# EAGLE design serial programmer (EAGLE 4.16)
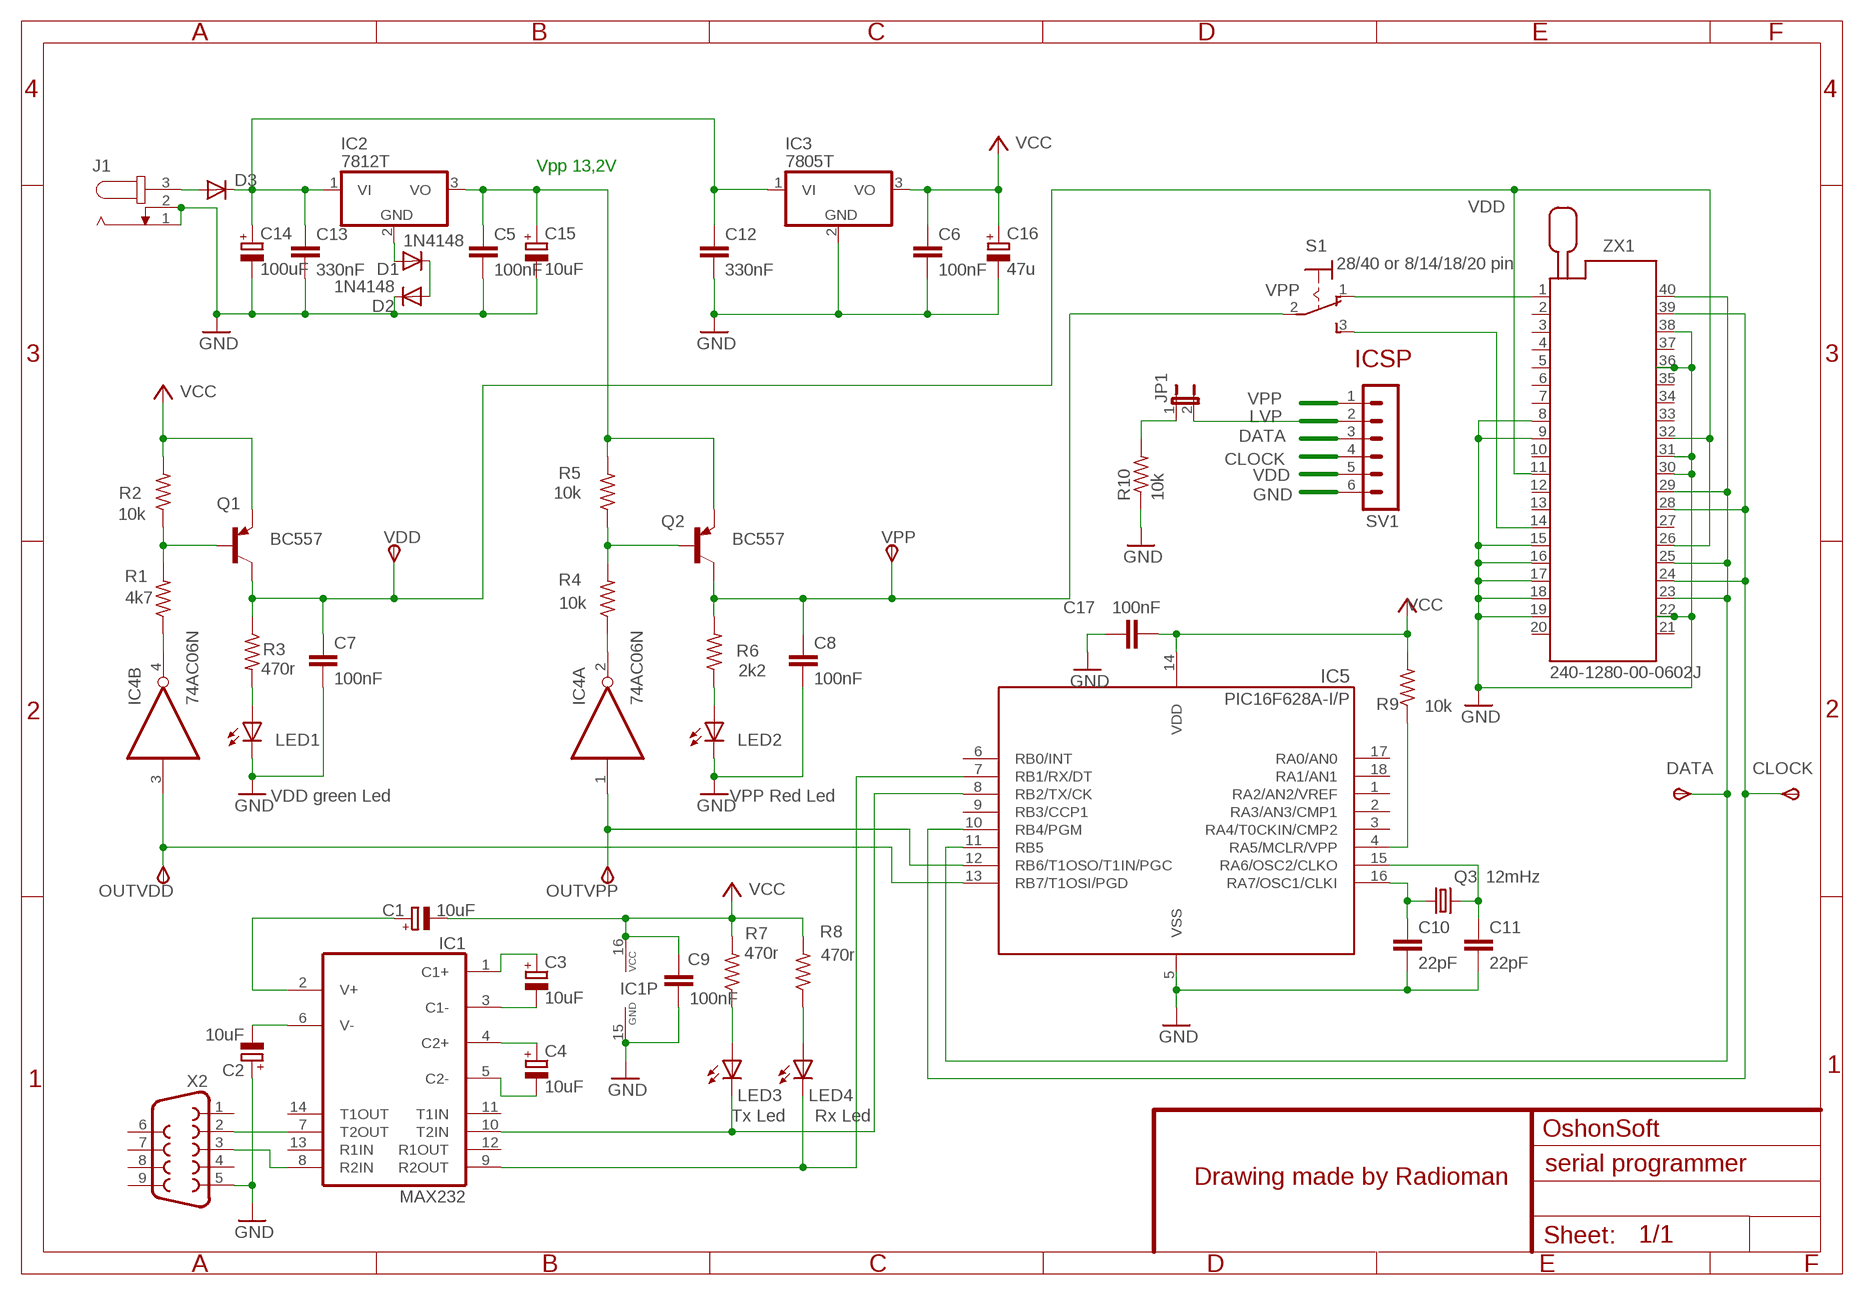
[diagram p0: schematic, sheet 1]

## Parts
C1  10uF  OVE_C_POL2MM_PAD10U25V  [E5-10,5]
C2  10uF  OVE_C_POL2MM_PAD10U25V  [E5-10,5]
C3  10uF  OVE_C_POL2MM_PAD10U25V  [E5-10,5]
C4  10uF  OVE_C_POL2MM_PAD10U25V  [E5-10,5]
C5  100nF  OVES_CGRID25X_050PAD15  [C025-025X050]
C6  100nF  OVES_CGRID25X_050PAD15  [C025-025X050]
C7  100nF  OVES_CGRID25X_050PAD15  [C025-025X050]
C8  100nF  OVES_CGRID25X_050PAD15  [C025-025X050]
C9  100nF  OVES_CGRID25X_050PAD15  [C025-025X050]
C10  22pF  OVES_CGRID25X_050PAD15  [C025-025X050]
C11  22pF  OVES_CGRID25X_050PAD15  [C025-025X050]
C12  330nF  OVES_CGRID75_2X_PAD20  [C075-052X106]
C13  330nF  OVES_CGRID75_2X_PAD20  [C075-052X106]
C14  100uF  OVE_C_POL2MM_PAD100U35V  [E3,5-8]
C15  10uF  OVE_C_POL2MM_PAD10U25V  [E5-10,5]
C16  47u  OVE_C_POL2MM_PAD47U35V  [E2,5-6E]
C17  100nF  OVES_CGRID25X_050PAD15  [C025-025X050]
CLOCK  OutVpp  TPSPAD1-13  [P1-13]
D1  1N4148  [DO35-10]
D2  1N4148  [DO35-10]
D3  1N4004  [DO41-10]
DATA  Data  TPSPAD1-13  [P1-13]
IC1  MAX232  [DIL16]
IC2  7812T  [TO220H]
IC3  7805T  [TO220H]
IC4  74AC06N  [DIL14]
IC5  PIC16F628A-I/P  [DIP18]
J1  JACK-PLUG1  [SPC4078]
JP1  JP1E  [JP1]
LED1  VDD green Led  LED3MM  [LED3MM]
LED2  VPP Red Led  LED3MM  [LED3MM]
LED3  Tx Led  LED3MM  [LED3MM]
LED4  Rx Led  LED3MM  [LED3MM]
OUTVDD  OutVdd  TPSPAD1-13  [P1-13]
OUTVPP  OutVpp  TPSPAD1-13  [P1-13]
Q1  BC557  [TO92-EBC]
Q2  BC557  [TO92-EBC]
Q3  12mHz  CRYSTALHC49S  [HC49/S]
R1  4k7  OVES_R10MM  [0207/10]
R2  10k  OVES_R10MM  [0207/10]
R3  470r  OVES_R10MM  [0207/10]
R4  10k  OVES_R10MM  [0207/10]
R5  10k  OVES_R10MM  [0207/10]
R6  2k2  OVES_R10MM  [0207/10]
R7  470r  OVES_R10MM  [0207/10]
R8  470r  OVES_R10MM  [0207/10]
R9  10k  OVES_R10MM  [0207/10]
R10  10k  OVES_R10MM  [0207/10]
S1  28/40 or 8/14/18/20 pin  320-916  [320-916]
SV1  MA06-1  [MA06-1]
VDD  Vdd  TPSPAD1-13  [P1-13]
VPP  Vpp  TPSPAD1-13  [P1-13]
X2  F09HP  [F09HP]
ZX1  240-1280-00-0602J  [240-1280-00-0602J]

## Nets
CLOCK: CLOCK.1(PP) IC5.10(RB4/PGM) SV1.4 ZX1.24 ZX1.28 ZX1.39
DATA: DATA.1(PP) IC5.11(RB5) SV1.3 ZX1.23 ZX1.25 ZX1.29 ZX1.40
GND: C2.+ C5.2 C6.2 C7.2 C8.2 C9.2 C10.2 C11.2 C12.2 C13.2 C14.- C15.- C16.- C17.1 D2.C IC1.15(GND) IC3.2(GND) IC5.5(VSS) J1.1 J1.2 LED1.K(C) LED2.K(C) R10.1 SV1.6 X2.5 ZX1.8 ZX1.9 ZX1.15 ZX1.16 ZX1.17 ZX1.18 ZX1.19 ZX1.22 ZX1.30 ZX1.31 ZX1.36 ZX1.38
LVP: JP1.2 SV1.2
N$1: D1.A IC2.2(GND)
N$2: C12.1 C13.1 C14.+ D3.C IC2.1(VI) IC3.1(VI)
N$3: D1.C D2.A
N$4: D3.A J1.3
N$5: LED3.A R7.1
N$6: Q1.B R1.2 R2.1
N$7: IC5.4(RA5/MCLR/VPP) R9.1
N$8: LED1.A R3.2
N$9: IC4.4(B:O) R1.1
N$10: Q2.B R4.2 R5.1
N$11: IC4.2(A:O) R4.1
N$12: C10.1 IC5.16(RA7/OSC1/CLKI) Q3.1
N$13: LED2.A R6.1
N$14: IC1.7(T2OUT) X2.2
N$15: IC1.8(R2IN) X2.3
N$16: LED4.A R8.1
N$17: IC1.10(T2IN) IC5.8(RB2/TX/CK) LED3.K(C)
N$18: IC1.9(R2OUT) IC5.7(RB1/RX/DT) LED4.K(C)
N$19: C1.+ IC1.2(V+)
N$20: C2.- IC1.6(V-)
N$21: C11.1 IC5.15(RA6/OSC2/CLKO) Q3.2
N$22: C4.- IC1.5(C2-)
N$23: C4.+ IC1.4(C2+)
N$24: C3.- IC1.3(C1-)
N$25: C3.+ IC1.1(C1+)
N$26: S1.1(O) ZX1.1
N$27: S1.3(S) ZX1.14
N$42: JP1.1 R10.2
OUTVDD: IC4.3(B:I) IC5.13(RB7/T1OSI/PGD) OUTVDD.1(PP)
OUTVPP: IC4.1(A:I) IC5.12(RB6/T1OSO/T1IN/PGC) OUTVPP.1(PP)
VCC: C1.- C6.1 C9.1 C16.+ C17.2 IC1.16(VCC) IC3.3(VO) IC5.14(VDD) Q1.E R2.2 R7.2 R8.2 R9.2
VDD: C7.1 Q1.C R3.1 SV1.5 VDD.1(PP) ZX1.11 ZX1.26 ZX1.32
VPP: C8.1 Q2.C R6.2 S1.2(P) SV1.1 VPP.1(PP)
VPP13.2V: C5.1 C15.+ IC2.3(VO) Q2.E R5.2
Unconnected: IC1.11(T1IN) IC1.12(R1OUT) IC1.13(R1IN) IC1.14(T1OUT) IC4.5(C:I) IC4.6(C:O) IC4.8(D:O) IC4.9(D:I) IC4.10(E:O) IC4.11(E:I) IC4.12(F:O) IC4.13(F:I) IC5.1(RA2/AN2/VREF) IC5.2(RA3/AN3/CMP1) IC5.3(RA4/T0CKIN/CMP2) IC5.6(RB0/INT) IC5.9(RB3/CCP1) IC5.17(RA0/AN0) IC5.18(RA1/AN1) X2.1 X2.4 X2.6 X2.7 X2.8 X2.9 ZX1.2 ZX1.3 ZX1.4 ZX1.5 ZX1.6 ZX1.7 ZX1.10 ZX1.12 ZX1.13 ZX1.20 ZX1.21 ZX1.27 ZX1.33 ZX1.34 ZX1.35 ZX1.37

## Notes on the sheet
- Vpp 13,2V
- ICSP
- OshonSoft
- Drawing made by Radioman

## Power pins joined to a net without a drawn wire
GND: IC4.7(P:GND)
VCC: IC4.14(P:VCC)

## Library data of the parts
C1-C4 C14-C16 = Oves-barebone:OVE_C_POL: De vanligaste med stora paddar.
C5-C13 C17 = Oves-barebone:OVES_C: De vanligaste med stora paddar.
CLOCK DATA OUTVDD OUTVPP VDD VPP = testpad:TPS: TEST PIN
D1 D2 = Oves-barebone:1N4148: DIODE
D3 = Oves-barebone:1N4004: DIODE
IC1 = maxim:MAX232: RS232 TRANSEIVER
IC2 IC3 = linear:78*: Positive VOLTAGE REGULATOR Source: http://cache.national.com/ds/LM/LM78L05.pdf http://www.fairchildsemi.com/ds/LM/LM7805.pdf
IC4 = 74xx-eu:74*06: Hex INVERTER, open collector high-voltage output
IC5 = pic:PIC16F628A-*/?: 18/20 pins, 2K prog, 224 RAM, 128 EEPROM, UART, 2 comp, 1 CCP
J1 = Oves-barebone:JACK-PLUG: DC POWER JACK Power Jack, DC, Right Angle, Through Hole, Rated 5A at 16VDC, PC Terminals Distributor: Farnell (www.Farnell.de) Drawing: 84N1161.pdf / 84N1162.pdf Manufacturer: SPC Technology (www.spctechnology.com) Type: SPC4077 / SPC 4078
JP1 = jumper:JP1E: JUMPER
LED1-LED4 = Oves-barebone:LED: LED
Q1 Q2 = transistor-pnp:BC557*: PNP Transistror
Q3 = crystal:CRYSTAL: CRYSTAL
R1-R10 = Oves-barebone:OVES_R: De vanligaste med stora paddar.
S1 = switch:320-916: TOGGLE SWITCH distributor RS Components
SV1 = con-lstb:MA06-1: PIN HEADER
X2 = con-subd:F09: SUB-D
ZX1 = con-3m:240-?-00-0602J: Zero Insertion Force Socked Source: http://www.3M.com/ehpd

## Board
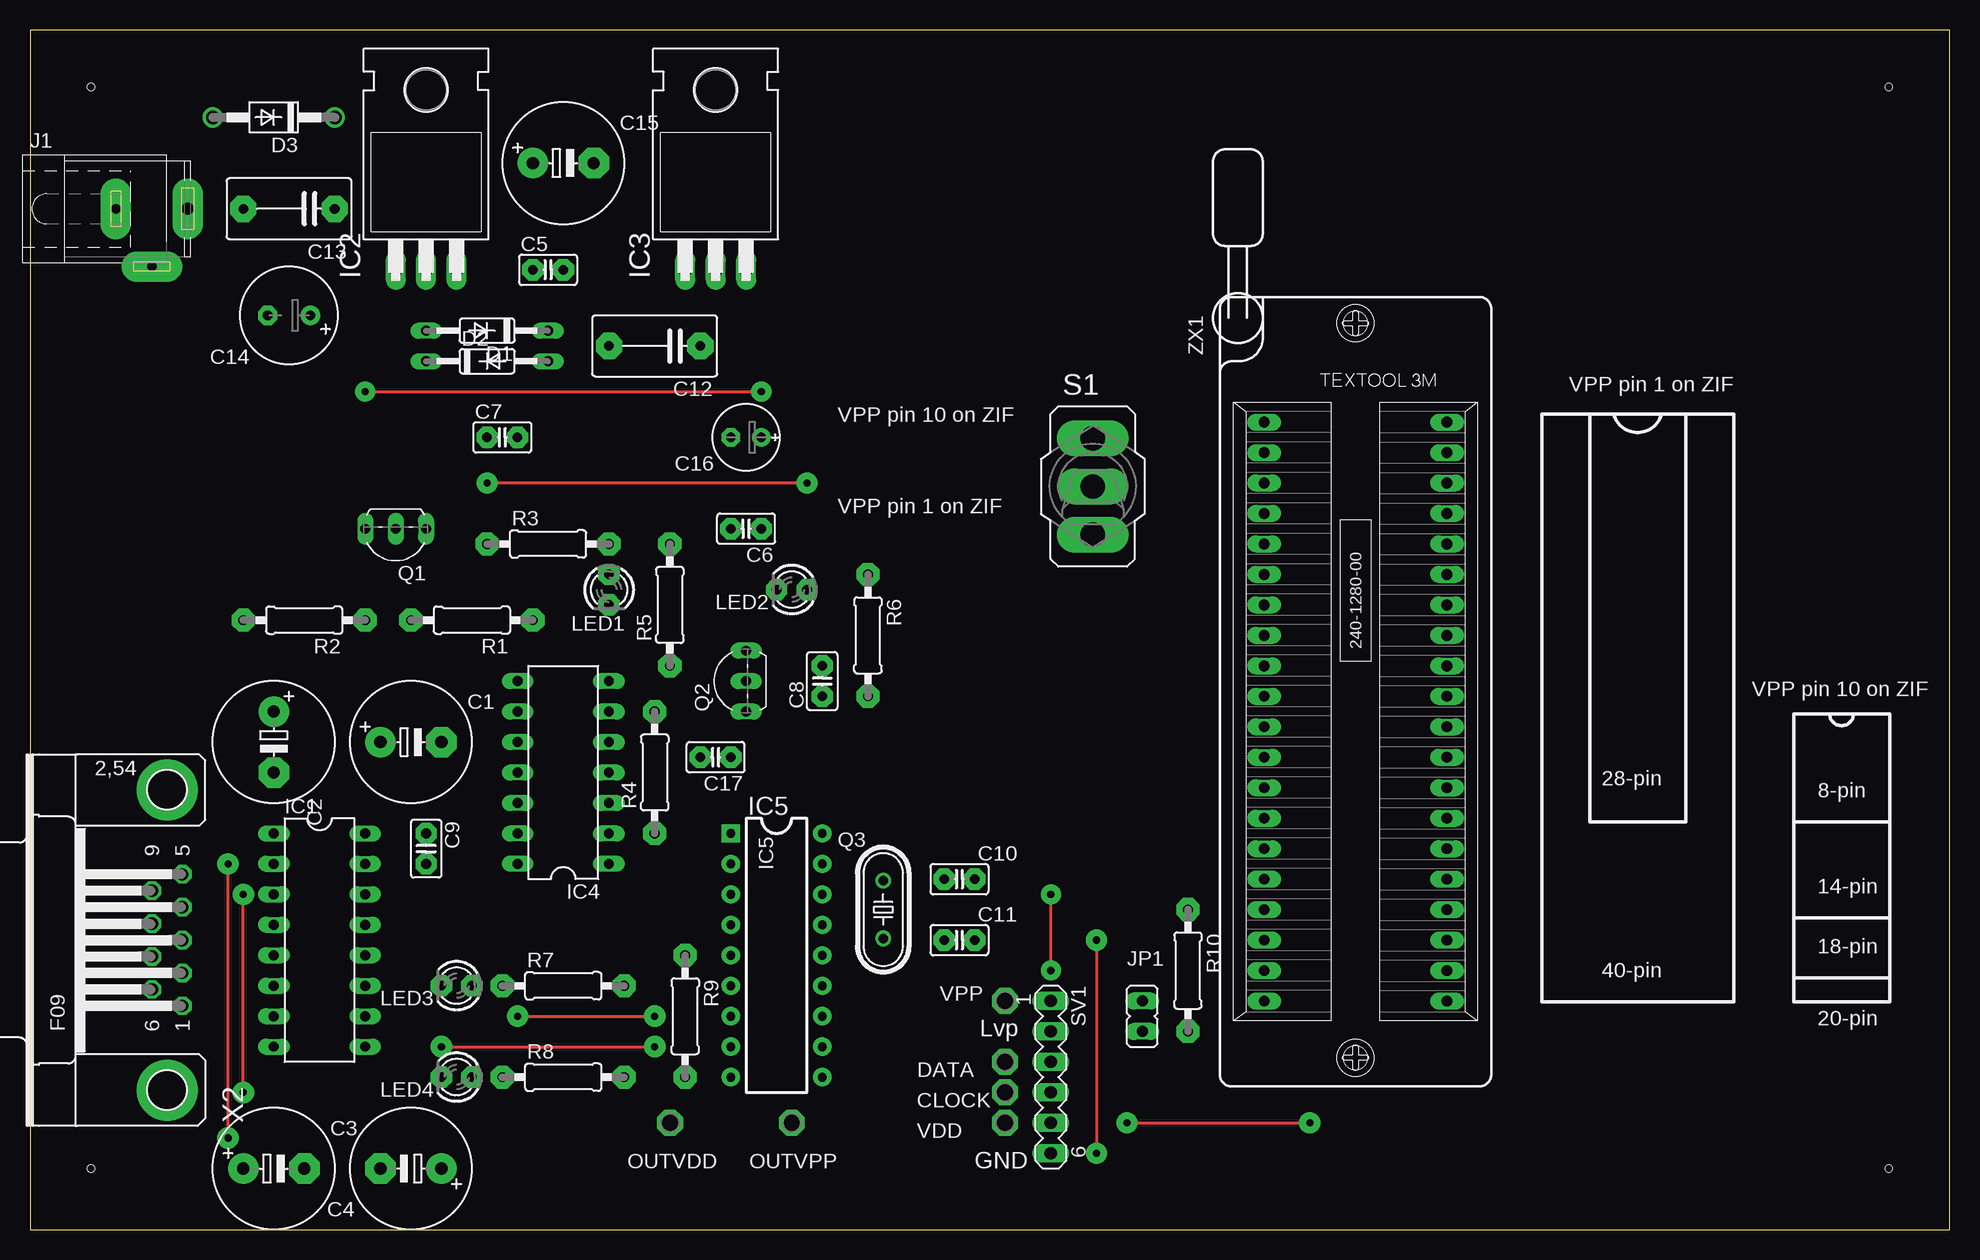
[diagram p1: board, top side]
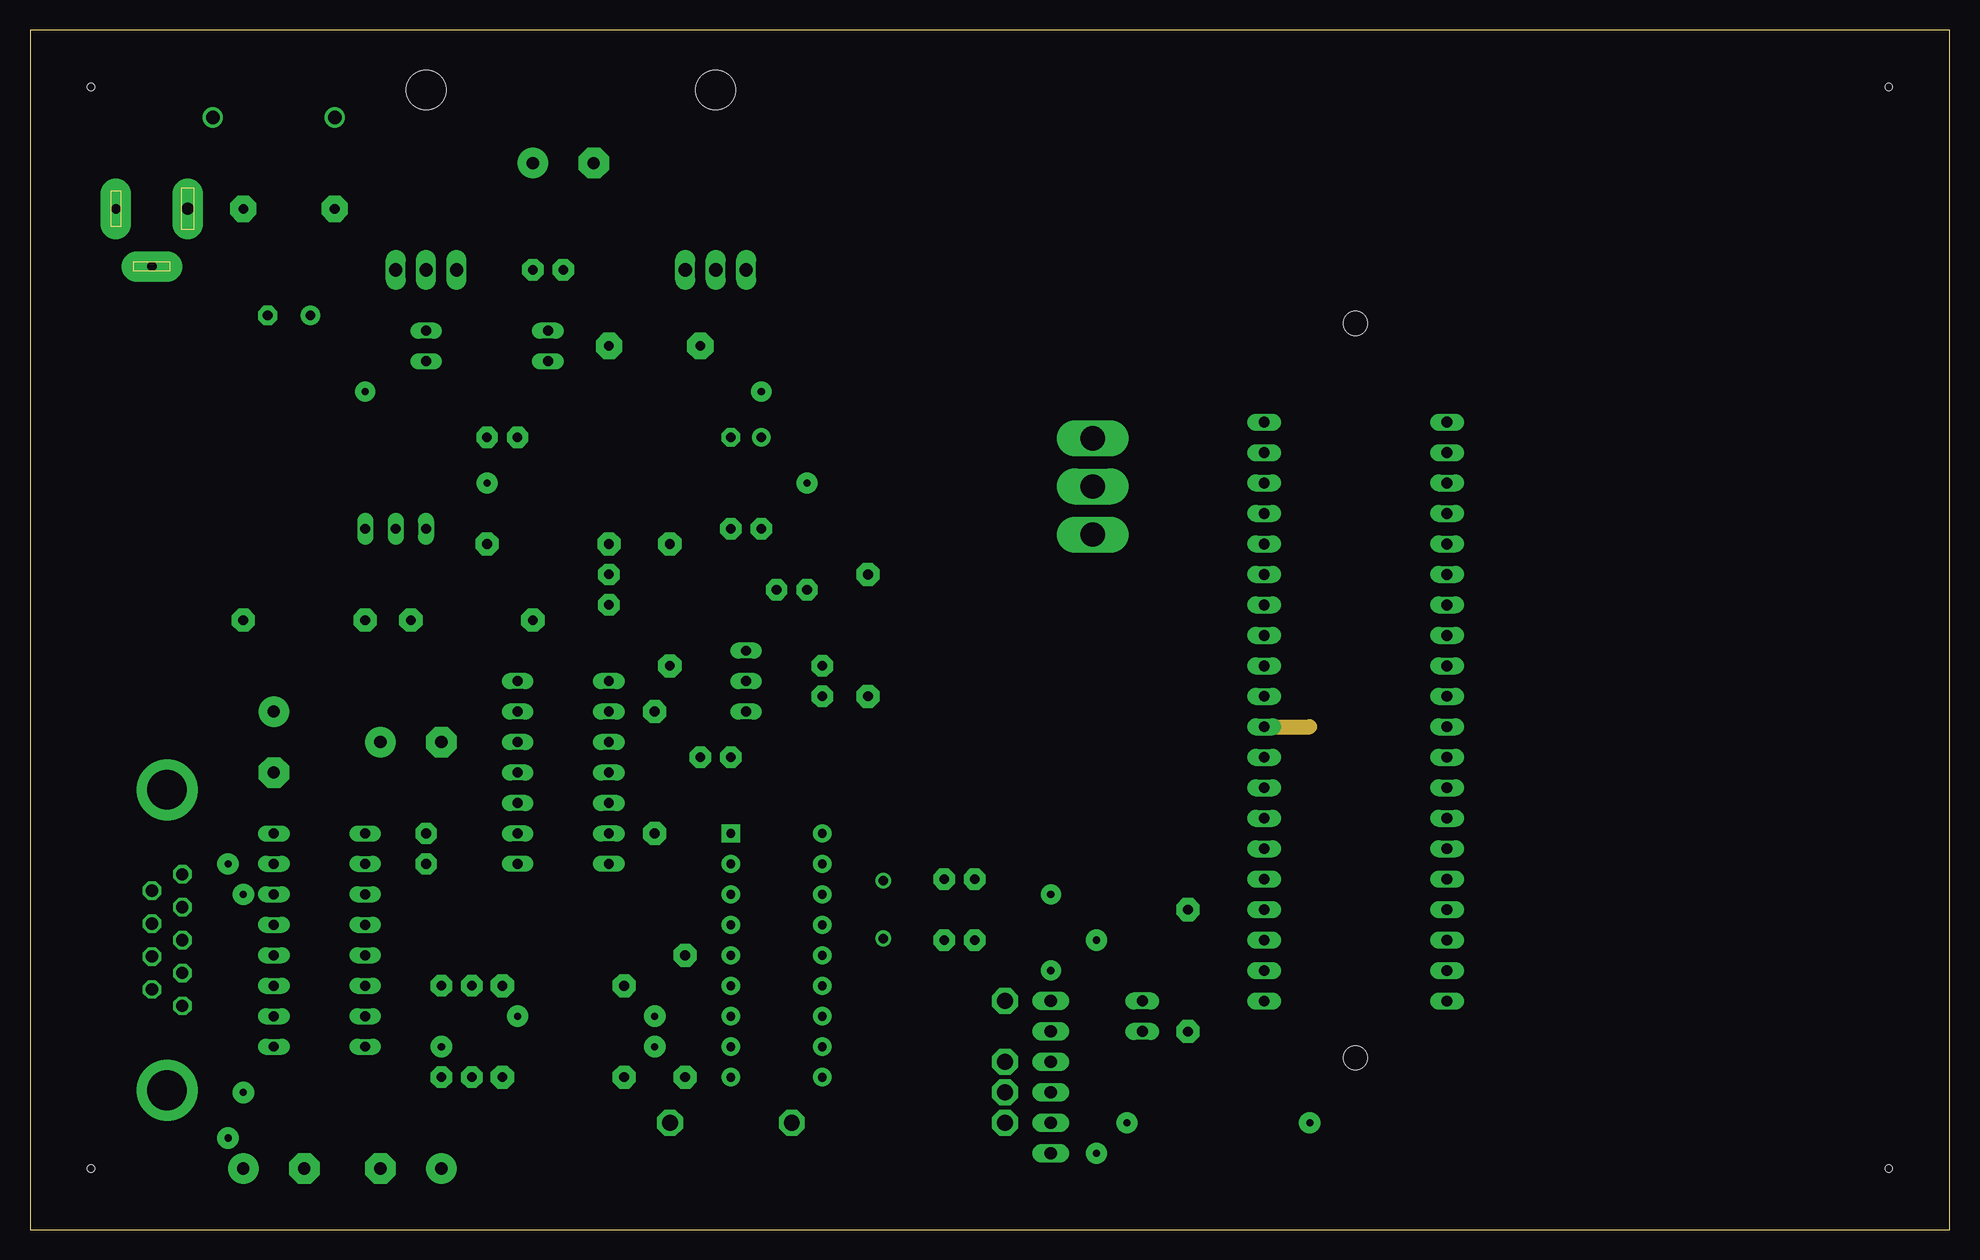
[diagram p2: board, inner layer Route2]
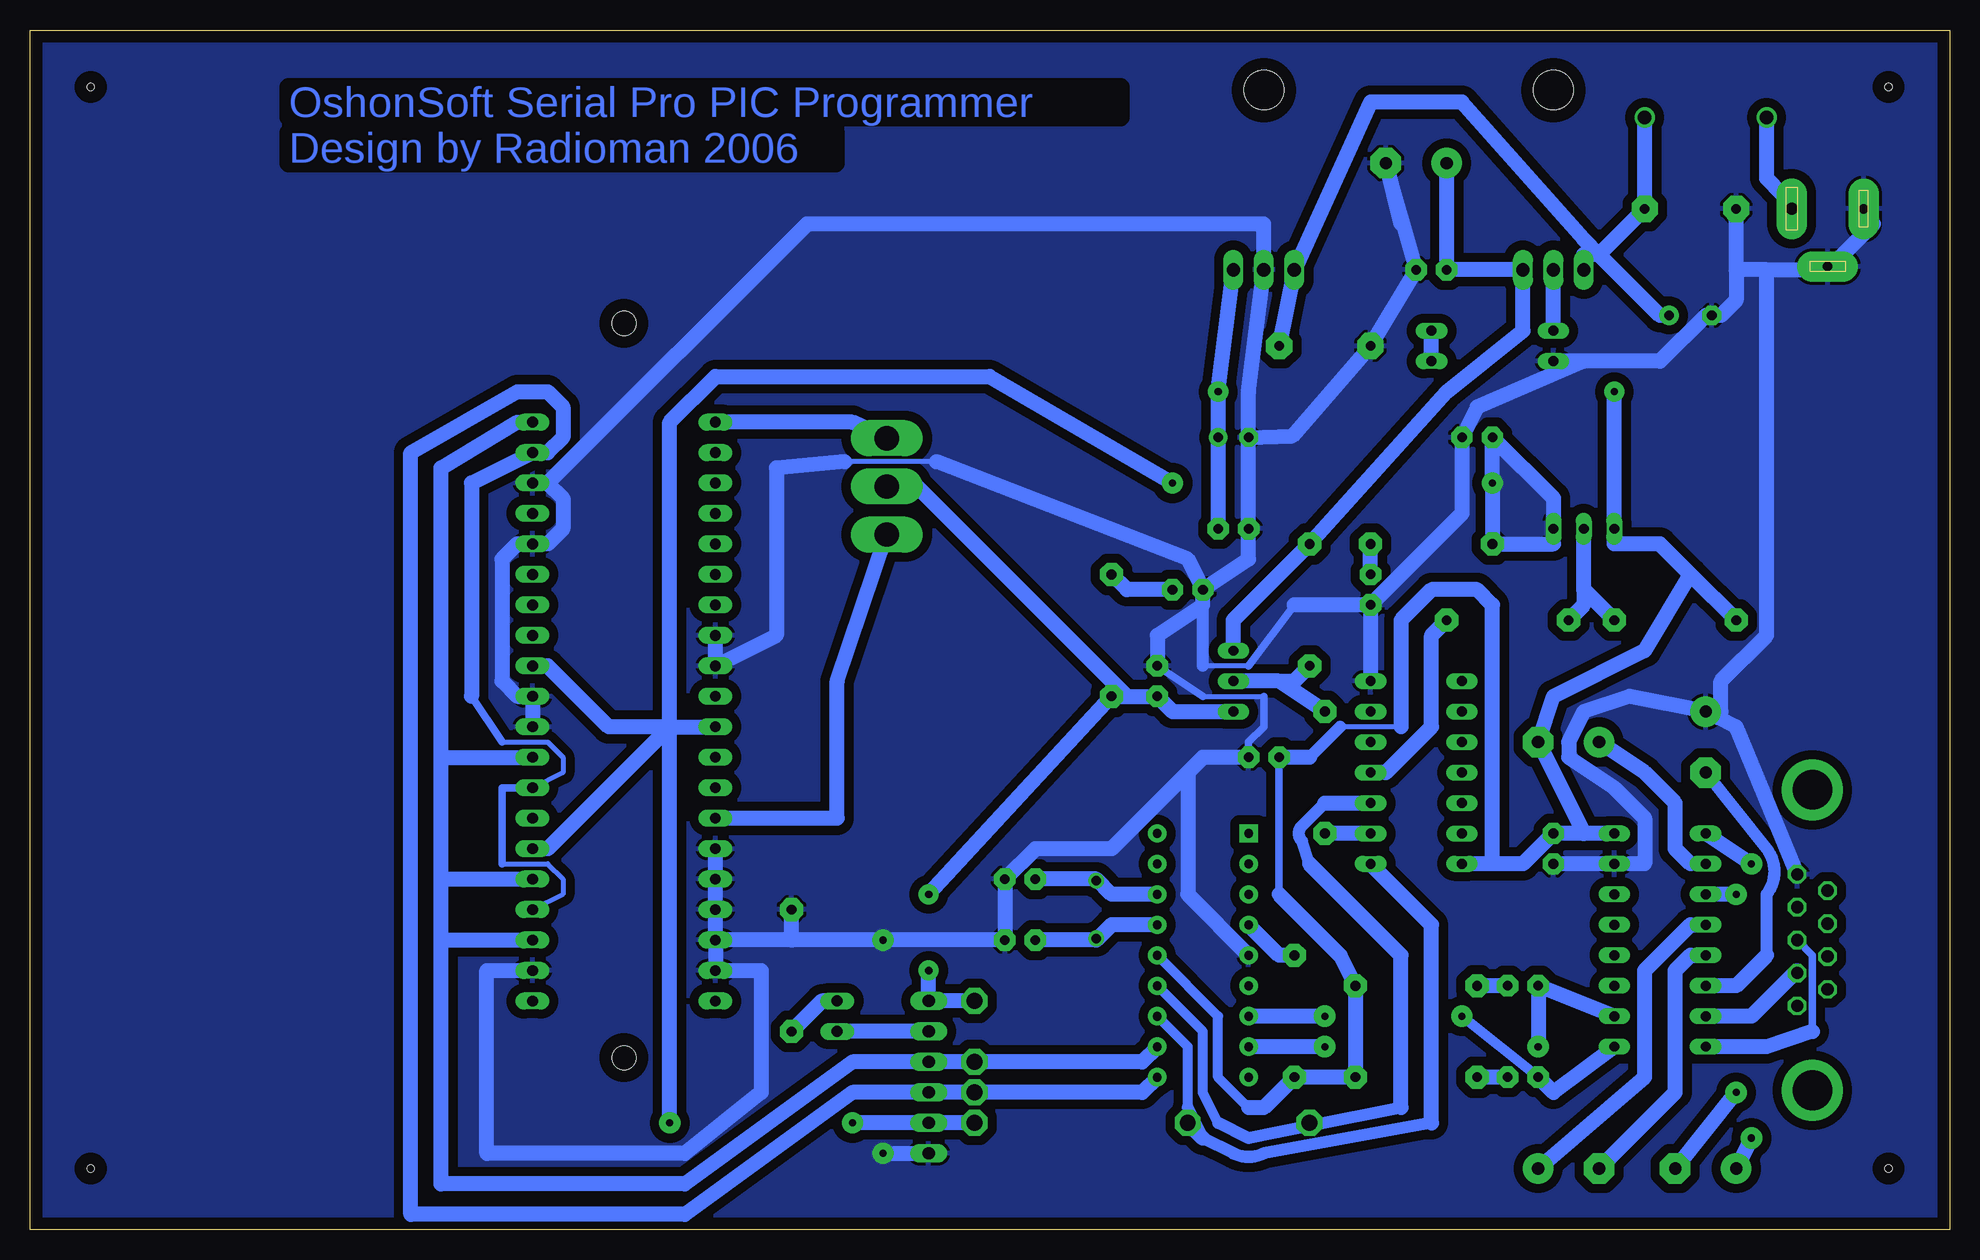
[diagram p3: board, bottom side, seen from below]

Size 160 x 100 mm. Coordinates in mm from the lower left corner, seen from the top.
Outline: 0,0 160,0 160,100 0,100 0,0
Copper layers (1*16): Top 0.035mm / dielectric 1.5mm / Bottom 0.035mm
Design rules "default": minimum track width 50mil, minimum drill 24mil, track to track 30mil, track to pad 30mil, pad to pad 30mil, via to via 30mil, smd to smd 8mil, copper to edge 40mil, drill to drill 8mil, minimum pad ring 10mil, minimum via ring 8mil, stop-mask expansion 4mil, vias tented up to drill 0mil, thermal gap 10mil
Holes 0.6 mm at 5.08,5.08 5.08,95.25 154.94,95.25 154.94,5.08

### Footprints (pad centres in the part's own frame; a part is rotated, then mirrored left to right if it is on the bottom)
E5-10,5 = drill 1.016 pad 2.54 round: + -2.54,0 | drill 1.016 pad 2.54 octagon: - 2.54,0
C025-025X050 = drill 0.8 pad 1.778 octagon: 1 -1.27,0; 2 1.27,0
C075-052X106 = drill 0.8 pad 2.184 octagon: 1 -3.81,0; 2 3.81,0
E3,5-8 = drill 0.813 pad 1.6 round: + -1.778,0 | drill 0.813 pad 1.6 octagon: - 1.778,0
E2,5-6E = drill 0.813 pad 1.575 round: + -1.27,0 | drill 0.813 pad 1.575 octagon: - 1.27,0
P1-13 = drill 1.321 pad 2.159 octagon: 1 0,0
DO35-10 = drill 0.813 long: A 5.08,0; C -5.08,0
DO41-10 = drill 1.118 round: A 5.08,0; C -5.08,0
DIL16 = drill 0.813 long: 1 -8.89,-3.81; 2 -6.35,-3.81; 3 -3.81,-3.81; 4 -1.27,-3.81; 5 1.27,-3.81; 6 3.81,-3.81; 7 6.35,-3.81; 8 8.89,-3.81; 9 8.89,3.81; 10 6.35,3.81; 11 3.81,3.81; 12 1.27,3.81; 13 -1.27,3.81; 14 -3.81,3.81; 15 -6.35,3.81; 16 -8.89,3.81
TO220H = drill 1.118 long: 1 -2.54,-10.16; 2 0,-10.16; 3 2.54,-10.16 | hole 3.302: 0,4.826
DIL14 = drill 0.813 long: 1 -7.62,-3.81; 2 -5.08,-3.81; 3 -2.54,-3.81; 4 0,-3.81; 5 2.54,-3.81; 6 5.08,-3.81; 7 7.62,-3.81; 8 7.62,3.81; 9 5.08,3.81; 10 2.54,3.81; 11 0,3.81; 12 -2.54,3.81; 13 -5.08,3.81; 14 -7.62,3.81
DIP18 = drill 0.737 pad 1.524 square: 1 -10.16,-3.81 | drill 0.737 pad 1.524 round: 2 -7.62,-3.81; 3 -5.08,-3.81; 4 -2.54,-3.81; 5 0,-3.81; 6 2.54,-3.81; 7 5.08,-3.81; 8 7.62,-3.81; 9 10.16,-3.81; 10 10.16,3.81; 11 7.62,3.81; 12 5.08,3.81; 13 2.54,3.81; 14 0,3.81; 15 -2.54,3.81; 16 -5.08,3.81; 17 -7.62,3.81; 18 -10.16,3.81
SPC4078 = drill 0.8 pad 2.54 long: 1 -3,0; 2 0,-4.8 | drill 1 pad 2.54 long: 3 3,0
JP1 = drill 0.914 long: 1 0,-1.27; 2 0,1.27
LED3MM = drill 0.8 pad 1.778 octagon: A -1.27,0; K 1.27,0
TO92-EBC = drill 0.813 long: B 0,-1.27; C -2.54,-1.27; E 2.54,-1.27
HC49/S = drill 0.813 round: 1 -2.413,0; 2 2.413,0
0207/10 = drill 0.813 pad 1.93 octagon: 1 -5.08,0; 2 5.08,0
320-916 = drill 2.007 long: 1 0,4.013; 2 0,0; 3 0,-4.013
MA06-1 = drill 1.016 long: 1 -6.35,0; 2 -3.81,0; 3 -1.27,0; 4 1.27,0; 5 3.81,0; 6 6.35,0
F09HP = drill 1.016 octagon: 1 -5.486,-1.27; 2 -2.743,-1.27; 3 0,-1.27; 4 2.743,-1.27; 5 5.486,-1.27; 6 -4.115,1.27; 7 -1.372,1.27; 8 1.372,1.27; 9 4.115,1.27 | drill 3.302 pad 5.08 round: G1 -12.522,0; G2 12.522,0
240-1280-00-0602J = drill 0.9 long: 1 -24.13,-7.62; 2 -21.59,-7.62; 3 -19.05,-7.62; 4 -16.51,-7.62; 5 -13.97,-7.62; 6 -11.43,-7.62; 7 -8.89,-7.62; 8 -6.35,-7.62; 9 -3.81,-7.62; 10 -1.27,-7.62; 11 1.27,-7.62; 12 3.81,-7.62; 13 6.35,-7.62; 14 8.89,-7.62; 15 11.43,-7.62; 16 13.97,-7.62; 17 16.51,-7.62; 18 19.05,-7.62; 19 21.59,-7.62; 20 24.13,-7.62; 21 24.13,7.62; 22 21.59,7.62; 23 19.05,7.62; 24 16.51,7.62; 25 13.97,7.62; 26 11.43,7.62; 27 8.89,7.62; 28 6.35,7.62; 29 3.81,7.62; 30 1.27,7.62; 31 -1.27,7.62; 32 -3.81,7.62; 33 -6.35,7.62; 34 -8.89,7.62; 35 -11.43,7.62; 36 -13.97,7.62; 37 -16.51,7.62; 38 -19.05,7.62; 39 -21.59,7.62; 40 -24.13,7.62 | hole 2: 28.86,0; -32.36,0

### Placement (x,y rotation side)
C1  31.75,40.64 0 top
C2  20.32,40.64 270 top
C3  20.32,5.08 0 top
C4  31.75,5.08 180 top
C5  43.18,80.01 0 top
C6  59.69,58.42 180 top
C7  39.37,66.04 0 top
C8  66.04,45.72 90 top
C9  33.02,31.75 270 top
C10  77.47,29.21 0 top
C11  77.47,24.13 0 top
C12  52.07,73.66 180 top
C13  21.59,85.09 180 top
C14  21.59,76.2 180 top
C15  44.45,88.9 0 top
C16  59.69,66.04 180 top
C17  57.15,39.37 180 top
CLOCK  81.28,11.43 0 top
D1  38.1,74.93 180 top
D2  38.1,72.39 0 top
D3  20.32,92.71 180 top
DATA  81.28,13.97 0 top
IC1  24.13,24.13 270 top
IC2  33.02,90.17 0 top
IC3  57.15,90.17 0 top
IC4  44.45,38.1 90 top
IC5  62.23,22.86 270 top
J1  10.16,85.09 0 top
JP1  92.71,17.78 180 top
LED1  48.26,53.34 270 top
LED2  63.5,53.34 180 top
LED3  35.56,20.32 180 top
LED4  35.56,12.7 180 top
OUTVDD  53.34,8.89 0 top
OUTVPP  63.5,8.89 0 top
Q1  30.48,57.15 180 top
Q2  58.42,45.72 90 top
Q3  71.12,26.67 270 top
R1  36.83,50.8 180 top
R2  22.86,50.8 180 top
R3  43.18,57.15 0 top
R4  52.07,38.1 90 top
R5  53.34,52.07 90 top
R6  69.85,49.53 270 top
R7  44.45,20.32 0 top
R8  44.45,12.7 0 top
R9  54.61,17.78 270 top
R10  96.52,21.59 270 top
S1  88.58,61.95 0 top
SV1  85.09,12.7 270 top
VDD  81.28,8.89 0 top
VPP  81.28,19.05 0 top
X2  11.43,24.13 90 top
ZX1  110.49,43.18 270 top

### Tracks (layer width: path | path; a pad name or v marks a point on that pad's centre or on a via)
CLOCK
  Bottom 0.406: ZX1.24 115.57,27.94 115.57,29.21 116.84,30.48 120.65,30.48 | ZX1.28 115.57,38.1 115.57,39.37 116.84,40.64 120.65,40.64
  Bottom 0.61: 123.19,44.45 120.65,40.64 | ZX1.28 120.65,36.83 120.65,30.48
  Bottom 1.27: IC5.10 67.31,11.43 CLOCK.1 SV1.4 91.44,11.43 105.41,1.27 128.27,1.27 128.27,64.77 119.38,69.85 116.84,69.85 115.57,68.58 115.57,66.04 116.84,64.77 ZX1.39 123.19,62.23 123.19,44.45
DATA
  Bottom 1.27: IC5.11 67.31,13.97 DATA.1 | 125.73,24.13 125.73,29.21 | 125.73,24.13 ZX1.23 | 125.73,39.37 125.73,63.5 119.38,67.31 ZX1.40 | 125.73,29.21 125.73,39.37 | 125.73,29.21 ZX1.25 | DATA.1 SV1.3 | SV1.3 91.44,13.97 105.41,3.81 125.73,3.81 125.73,24.13 | DATA.1 SV1.3 | 125.73,39.37 ZX1.29
GND  (via drill 0.6 pad 1.78)
  Top 0.254: v88.9,24.13 v88.9,6.35
  Bottom 0.406: 58.42,46.99 62.23,46.99 | 62.23,44.45 57.15,44.45 | 84.45,64.01 92.08,64.01
  Bottom 0.61: 54.61,52.07 58.42,46.99 | C17.1 58.42,40.64 57.15,41.91 57.15,44.45 | C8.2 62.23,44.45
  Bottom 1.016: 62.23,46.99 62.23,52.07 | 26.67,30.48 IC1.15
  Bottom 1.27: ZX1.30 ZX1.31 119.38,44.45 120.65,45.72 120.65,55.88 119.38,57.15 ZX1.36 116.84,57.15 115.57,58.42 115.57,60.96 116.84,62.23 | ZX1.8 ZX1.9 97.79,49.53 97.79,63.5 92.08,64.01 | IC5.5 63.5,27.94 63.5,38.1 | ZX1.15 ZX1.16 ZX1.17 ZX1.18 | ZX1.18 ZX1.19 99.06,21.59 99.06,11.43 105.41,6.35 121.92,6.35 121.92,21.59 ZX1.22 | 96.52,24.13 v88.9,24.13 C11.2 C10.2 76.2,31.75 69.85,31.75 63.5,38.1 | 96.52,24.13 ZX1.18 | IC1.15 C9.2 | LED1.K IC4.7 | C8.2 66.04,49.53 62.23,52.07 LED2.K | 30.48,72.39 D2.C | J1.1 6.35,83.82 8.89,81.28 J1.2 11.43,80.01 15.24,80.01 | 30.48,72.39 24.13,72.39 20.32,76.2 C14.- 19.05,76.2 17.78,77.47 17.78,80.01 | 17.78,80.01 C13.2 | 15.24,80.01 17.78,80.01 | 45.72,83.82 C15.- C5.2 C12.2 54.77,66.15 C16.- | 19.3,42.67 17.78,41.91 X2.5 | 19.3,42.67 C2.+ 26.67,44.45 30.48,43.18 31.75,40.64 31.75,39.37 27.94,36.83 25.4,34.29 25.4,30.48 26.67,30.48 | LED1.K 54.61,52.07 | LED1.K IC4.7 | LED1.K IC4.7 | C6.2 C16.- | C6.2 C16.- | C16.- 58.42,69.85 IC3.2 57.15,83.82 95.25,83.82 116.84,62.23 | 30.48,72.39 39.37,68.58 C7.2 40.64,59.69 LED1.K | C17.1 62.23,39.37 63.5,38.1 | 96.52,24.13 R10.1 | v88.9,6.35 SV1.6 | 116.84,62.23 ZX1.38 | 15.24,80.01 15.24,49.53 19.05,45.72 19.05,43.18 19.3,42.67 | LED2.K 58.42,55.88 C6.2 | 84.45,64.01 63.5,55.88 LED2.K
  pour Bottom: 0,0 160.02,0 160.02,100.33 0,100.33
LVP
  Bottom 1.27: SV1.2 JP1.2
N$1
  Bottom 1.27: D1.A IC2.2
N$2
  Bottom 1.27: 29.21,81.28 30.48,81.28 IC2.1 | 29.21,81.28 30.48,82.55 40.64,93.98 48.26,93.98 IC3.1 C12.1 | 29.21,81.28 24.13,76.2 C14.+ | D3.C C13.1 29.21,81.28
N$3
  Bottom 1.27: D2.A D1.C
N$4
  Bottom 1.27: D3.A 15.24,87.63 13.97,86.36 J1.3
N$5
  Bottom 1.27: LED3.A R7.1
N$6
  Bottom 1.27: 30.48,53.34 30.48,52.07 R1.2 | 30.48,53.34 Q1.B | R2.1 30.48,53.34
N$7
  Bottom 1.27: IC5.4 55.88,22.86 R9.1
N$8
  Bottom 1.27: LED1.A R3.2
N$9
  Bottom 1.27: R1.1 43.18,49.53 43.18,41.91 46.99,38.1 IC4.4
N$10
  Bottom 1.27: 55.88,45.72 54.61,45.72 R5.1 | 55.88,45.72 Q2.B | R4.2 55.88,45.72
N$11
  Bottom 1.27: IC4.2 R4.1
N$12
  Bottom 1.27: 71.12,29.21 C10.1 | IC5.16 69.85,27.94 71.12,29.21 | 71.12,29.21 Q3.1
N$13
  Bottom 1.27: LED2.A 68.58,53.34 R6.1
N$14
  Bottom 1.27: IC1.7 16.51,17.78 12.7,21.59 X2.2
N$15
  Bottom 0.61: 11.43,16.51 11.43,22.86 X2.3
  Bottom 1.27: IC1.8 15.24,15.24 11.43,16.51
N$16
  Bottom 1.27: LED4.A R8.1
N$17  (via drill 0.6 pad 1.78)
  Top 0.254: v34.29,15.24 v52.07,15.24
  Bottom 1.27: IC1.10 LED3.K v34.29,15.24 | v52.07,15.24 IC5.8
N$18  (via drill 0.6 pad 1.78)
  Top 0.254: v40.64,17.78 v52.07,17.78
  Bottom 0.813: LED4.K v40.64,17.78
  Bottom 1.27: LED4.K 33.02,11.43 IC1.9 | v52.07,17.78 IC5.7
N$19
  Bottom 1.016: IC1.2 21.59,30.48
  Bottom 1.27: C1.+ 25.4,38.1 22.86,35.56 22.86,31.75 21.59,30.48
N$20
  Bottom 1.016: C2.- 15.24,31.75 arc77 15.24,27.94 15.24,22.86
  Bottom 1.27: 15.24,22.86 17.78,20.32 IC1.6
N$21
  Bottom 1.27: 71.12,24.13 C11.1 | IC5.15 69.85,25.4 71.12,24.13 | 71.12,24.13 Q3.2
N$22
  Bottom 1.27: IC1.5 21.59,22.86 22.86,21.59 22.86,11.43 C4.-
N$23
  Bottom 1.27: IC1.4 21.59,25.4 25.4,21.59 25.4,12.7 C4.+
N$24  (via drill 0.6 pad 1.78)
  Top 0.254: v17.78,11.43 v17.78,27.94
  Bottom 1.27: v17.78,27.94 IC1.3 | C3.- v17.78,11.43
N$25  (via drill 0.6 pad 1.78)
  Top 0.254: v16.51,7.62 v16.51,30.48
  Bottom 1.27: v16.51,30.48 IC1.1 | C3.+ v16.51,7.62
N$26
  Bottom 1.27: ZX1.1 91.44,67.31 S1.1
N$27
  Bottom 1.27: S1.3 92.71,45.72 92.71,34.29 ZX1.14
N$38  (via drill 0.6 pad 1.68)
  other vias: 60.96,69.85
N$40  (via drill 0.6 pad 1.68)
  other vias: 27.94,69.85
N$42
  Bottom 1.27: R10.2 93.98,19.05 JP1.1
N$44  (via drill 0.6 pad 1.68)
  other vias: 85.09,21.59
N$45  (via drill 0.6 pad 1.68)
  other vias: 85.09,27.94
OUTVDD
  Bottom 0.254: OUTVDD.1 55.24,8.26
  Bottom 0.813: 60.96,8.89 62.23,11.43 62.23,16.51 IC5.13
  Bottom 1.016: 52.07,35.56 53.98,33.66 arc-90 53.98,32.38 53.34,30.48 | 45.72,10.16 53.29,8.65 55.98,8.11 58.42,7.62 60.96,8.89
  Bottom 1.27: 52.07,35.56 IC4.3 | 53.34,30.48 45.72,22.86 45.72,10.16 | 53.29,8.65 OUTVDD.1
OUTVPP
  Bottom 0.813: IC5.12 63.5,15.24 63.5,10.16
  Bottom 1.016: 63.5,10.16 62.23,7.62 59.69,6.35 arc-53 57.15,6.35 43.18,8.89
  Bottom 1.27: 43.18,8.89 43.18,25.4 IC4.1 | 62.23,7.62 OUTVPP.1
VCC  (via drill 0.6 pad 1.68)
  Top 0.254: v27.94,69.85 v60.96,69.85
  Bottom 0.406: 45.72,41.91 50.8,41.91
  Bottom 0.61: C17.2 55.88,27.94
  Bottom 0.813: IC5.14 60.96,17.78 60.96,12.7 58.42,10.16
  Bottom 1.016: 50.8,41.91 53.34,39.37
  Bottom 1.27: 21.59,54.61 R2.2 | 21.59,54.61 24.13,57.15 27.94,57.15 Q1.E v27.94,69.85 | 58.42,10.16 57.15,10.16 R9.2 R8.2 R7.2 50.8,22.86 55.88,27.94 | IC1.16 30.48,33.02 | 30.48,33.02 C9.1 35.56,30.48 38.1,30.48 | 21.59,54.61 25.4,48.26 33.02,44.45 C1.- 30.48,33.02 | v60.96,69.85 IC3.3 | v60.96,69.85 C16.+ C6.1 v60.96,69.85 | 38.1,30.48 IC4.14 | 38.1,30.48 38.1,52.07 39.37,53.34 43.18,53.34 45.72,50.8 45.72,41.91 | 53.34,39.37 C17.2
VDD  (via drill 0.6 pad 1.78)
  Top 0.254: v64.77,62.23 v38.1,62.23 | v91.44,8.89 v106.68,8.89
  Route2 1.27: ZX1.11 106.68,41.91
  Bottom 1.27: VDD.1 SV1.5 v91.44,8.89 | 106.68,41.91 111.76,41.91 116.84,46.99 ZX1.32 | 106.68,41.91 116.84,31.75 ZX1.26 | 106.68,41.91 106.68,67.31 102.87,71.12 80.01,71.12 v64.77,62.23 | 106.68,41.91 ZX1.11 | v106.68,8.89 106.68,41.91 | R3.1 33.02,57.15 Q1.C 33.02,60.96 C7.1 v38.1,62.23 R3.1
  pour Bottom: 33.02,57.15 33.02,60.96 38.1,66.04 38.1,57.15
VPP  (via drill 0.6)
  Top 0.254: v85.09,21.59 v85.09,27.94
  Bottom 1.27: Q2.C 64.77,43.18 C8.1 68.58,44.45 | 68.58,44.45 R6.2 v85.09,27.94 | SV1.1 VPP.1 SV1.1 | SV1.1 v85.09,21.59 | 68.58,44.45 86.36,62.23 S1.2
VPP13.2V
  Bottom 1.27: C15.+ C5.1 IC2.3 35.56,74.93 41.91,69.85 R5.2 59.69,50.8 Q2.E

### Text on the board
Bottom: OshonSoft Serial Pro PIC Programmer | Design by Radioman 2006
tPlace: VPP pin 1 on ZIF | VPP pin 10 on ZIF | VPP pin 1 on ZIF | VPP pin 10 on ZIF | 28-pin | 8-pin | 14-pin | 18-pin | 40-pin | 20-pin | Lvp | GND
tOrigins: -----> | <-----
